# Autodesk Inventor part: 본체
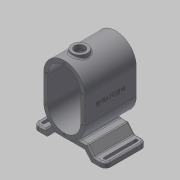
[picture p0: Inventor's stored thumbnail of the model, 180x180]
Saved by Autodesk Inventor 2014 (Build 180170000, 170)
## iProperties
Created: 2016-12
Part Number: 본체
Material: 일반
Document SubType Name: Modeling
Designer: mduedu
Density: 1 g/cm^3
Appearance: 기본값
Mass: 375.358 g
Surface Area: 965.791 cm^2
Volume: 375.358 cm^3
Author: mduedu
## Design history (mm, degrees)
sketch "스케치1"
  geometry: L1 (40, -25)-(40, 25); L2 (-40, 25)-(-40, -25); L3 (-40, -25)-(40, 25); L4 (40, -25)-(-40, 25); L5 (0, 25)-(0, -25); A1 r 40 centre (0, 25) between (40, 25) and (-40, 25); A2 r 40 centre (0, -25) between (-40, -25) and (40, -25); 1 further point
  constraints: 10 end point, 4 point on circle, 3 tangent, 2 centre point, 2 midpoint, 2 parallel, 1 vertical
  dimensions: "d0" = 130 dimension on A2 A1; "d2" = 80 distance between parallel lines of L1 L2
extrude "돌출1" new body sketch "스케치1" stored distance "d3" = 100; taper "d4" = 0 deg
feature "쉘1" dims "d5" = 8
sketch "스케치15"
  geometry: L1 (-35, -64.5)-(35, -64.5); L2 (-35, -64.5)-(-47.586, -79.5); L3 (-47.586, -79.5)-(-70, -79.5); L4 (0, -64.5)-(0, 0); L5 (35, -64.5)-(47.586, -79.5); L6 (47.586, -79.5)-(70, -79.5); L7 (70, -89.5)-(42.923, -89.5); L8 (42.923, -89.5)-(30.337, -74.5); L9 (30.337, -74.5)-(-30.337, -74.5); L10 (-30.337, -74.5)-(-42.923, -89.5); L11 (-42.923, -89.5)-(-70, -89.5); L12 (-70, -79.5)-(-70, -89.5); L13 (70, -79.5)-(70, -89.5); A1 r 40 centre (0, -25) between (-40, -25) and (40, -25) reference; 1 further point
  constraints: 26 end point, 2 parallel, 2 perpendicular, 2 symmetric about line, 1 coincident, 1 horizontal, 1 midpoint, 1 vertical, 4 other
  dimensions: "d83" = 10 distance between parallel lines of L9 L1; "d85" = 140 distance between parallel lines of L13 L12; "d86" = 70 distance of L1.start L1.end; "d87" = 25 distance between parallel lines of L11 L1; "d88" = 130 deg angle of L1 L2; "d106" = 0.5 distance edge to line of A1 L1
extrude "돌출6" new body sketch "스케치15" stored distance "d89" = 80; taper "d90" = 0 deg
fillet "모깎기13" dims "d101" = 3
fillet "모깎기15" dims "d103" = 3
fillet "모깎기16" dims "d104" = 10
fillet "모깎기17" dims "d105" = 3
feature "결합2"
  node "솔리드2"
fillet "모깎기18" dims "d107" = 3
sketch "스케치16"
  geometry: L1 (8.015, 67)-(8.015, 7); L2 (14.015, 67)-(14.015, 7); A1 r 10 centre (11.015, 67) between (21.015, 67) and (11.015, 77) reference; A2 r 10 centre (11.015, 7) between (11.015, -3) and (21.015, 7) reference; A3 r 3 centre (11.015, 67) between (8.015, 67) and (14.015, 67); A4 r 3 centre (11.015, 7) between (8.015, 7) and (14.015, 7); 1 further point
  constraints: 4 end point, 4 point on circle, 4 tangent, 2 centre point, 2 coincident
  dimensions: "d108" = 6 diameter of A3; "d109" = 6 diameter of A4
extrude "돌출7" cut sketch "스케치16" stored distance "d110" = 80; taper "d111" = 0 deg
node "작업 평면1"
sketch "스케치9"
  geometry: 1 further point
sketch "스케치7"
  geometry: L1 (40, 50)-(-40, 50) reference; C1 r 15 at (0, 20); 1 further point
  constraints: 1 centre point, 1 vertical alignment
  dimensions: "d40" = 30 diameter of C1; "d41" = 30 distance from line of C1.centre L1
extrude "돌출4" join sketch "스케치7" stored distance "d42" = 80; taper "d43" = 0 deg
hole "구멍2" diameter "d46" = 20; stored, may be unused: countersink angle "d50" = 90 deg, drill point angle "d52" = 118 deg; dims "d44" = 10, "d45" = 10, "d47" = 6, "d48" = 4, "d49" = 2, "d51" = 8
fillet "모깎기4" dims "d53" = 3
node "작업 평면2"
sketch "스케치8"
  geometry: C1 r 15 at (0, 0) reference; C2 r 15 at (0, 0); 1 further point
  constraints: 1 centre point, 1 coincident
  dimensions: "d55" = 30 diameter of C2
extrude "돌출5" cut sketch "스케치8" stored distance "d56" = 80; taper "d57" = 0 deg
chamfer "모따기1" distance "d58" = 1; stored, may be unused: second distance "d59" = 2, angle "d60" = 45 deg
sketch "스케치10"
  geometry: 2 further points
  constraints: 1 coincident, 1 other
feature "엠보싱1" sketch "스케치10" dims "d0" = 130, "d2" = 80, "d61" = 0.5, "d62" = 0
sketch "스케치11"
  geometry: 1 further point
  constraints: 1 other
hole "구멍3" sketch "스케치11" at (0, 60) diameter "d63" = 3.242; stored, may be unused: countersink angle "d67" = 90 deg, drill point angle "d69" = 120 deg; dims "d64" = 8.6, "d65" = 4, "d66" = 2, "d68" = 10.6
sketch "스케치12"
  geometry: 1 further point
  constraints: 1 other
hole "구멍5" sketch "스케치12" at (0, 60) diameter "d70" = 3.242; stored, may be unused: countersink angle "d74" = 90 deg, drill point angle "d76" = 120 deg; dims "d71" = 8.6, "d72" = 4, "d73" = 2, "d75" = 10.6
node "솔리드1"
mirror "대칭2"
pattern_linear "직사각형 패턴1"
pattern_linear "직사각형 패턴2"
sketch "스케치13"
  geometry: L1 (-40, 25)-(-40, -25) reference; L2 (40, -25)-(40, 25) reference; L3 (35, 25)-(35, -25); L4 (-35, -25)-(-35, 25); A1 r 40 centre (0, 25) between (40, 25) and (-40, 25) reference; A2 r 40 centre (0, -25) between (-40, -25) and (40, -25) reference; A3 r 35 centre (0, 25) between (35, 25) and (-35, 25); A4 r 35 centre (0, -25) between (-35, -25) and (35, -25); 2 further points
  constraints: 5 point on circle, 4 end point, 2 centre point, 3 other
  dimensions: "d77" = 5 distance between parallel lines of L3 L2
sketch "스케치14"
  geometry: L1 (-40, 25)-(-40, -25) reference; L2 (40, -25)-(40, 25) reference; L3 (35, 25)-(35, -25); L4 (-35, -25)-(-35, 25); A1 r 40 centre (0, 25) between (40, 25) and (-40, 25) reference; A2 r 40 centre (0, -25) between (-40, -25) and (40, -25) reference; A3 r 35 centre (0, 25) between (35, 25) and (-35, 25); A4 r 35 centre (0, -25) between (-35, -25) and (35, -25); 2 further points
  constraints: 5 point on circle, 4 end point, 2 centre point, 3 other
  dimensions: "d80" = 5 distance between parallel lines of L2 L3
other parameters: "d54" = -8
